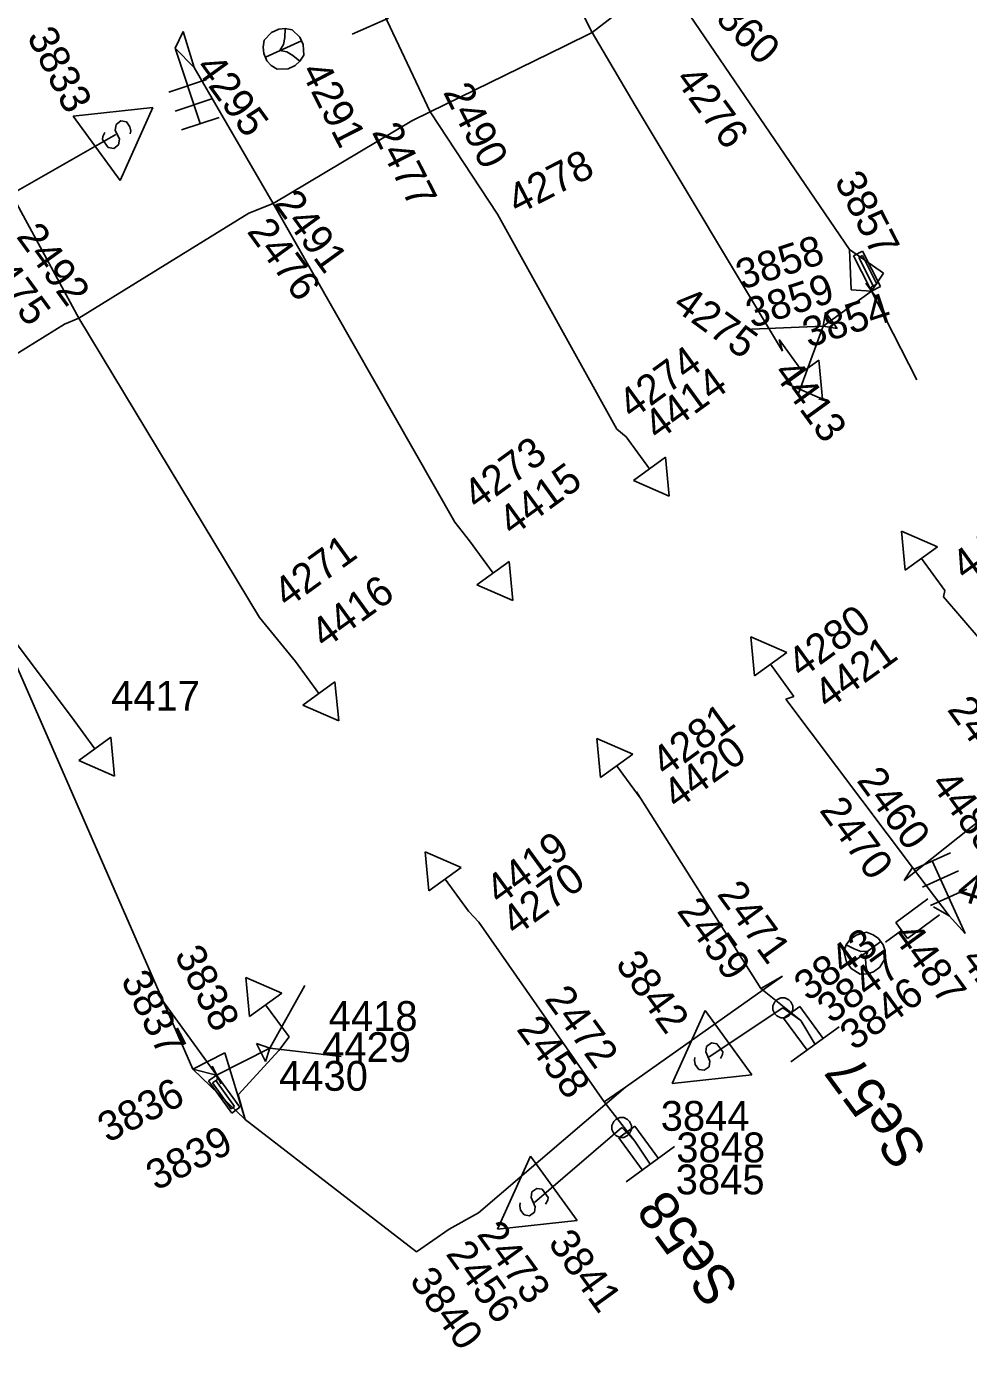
# Model space of a CAD drawing. Extents: x -535557 to -534097, y -1142175 to -1136716.
# Drawn here: x -534895.4 to -534871.72, y -1139172.92 to -1139139.7 of the extents above; entities that cross this region are included whole.
import ezdxf

# ---------------------------------------------------------------- set-up
doc = ezdxf.new("R2010")
doc.units = 0
doc.layers.add('Default', color=7, linetype='Continuous')
doc.layers.add('SS_SZDC', color=7, linetype='Continuous')

# ---------------------------------------------------------------- blocks, each defined once
blk = doc.blocks.new('POINT_DISPLAY')
at = {"layer": 'Default'}
blk.add_line((0, 0), (0, 0), dxfattribs=at)

msp = doc.modelspace()

# ---------------------------------------------------------------- linework, layer by layer
at = {"layer": 'SS_SZDC'}
for p, q in [((-534881.18, -1139139.86), (-534882.97, -1139136.26)), ((-534886.949, -1139138.25), (-534885.25, -1139141.85)), ((-534881.18, -1139139.86), (-534879.569, -1139138.61)), ((-534878.97, -1139139.069), (-534874.71, -1139145.309)), ((-534889.236, -1139139.855), (-534889.054, -1139139.773)), ((-534889.054, -1139139.773), (-534888.897, -1139139.756)), ((-534888.906, -1139139.98), (-534888.897, -1139139.756)), ((-534888.897, -1139139.756), (-534888.719, -1139139.786)), ((-534888.719, -1139139.786), (-534888.525, -1139139.973)), ((-534886.296, -1139139.498), (-534887.211, -1139139.901)), ((-534891.659, -1139140.25), (-534891.46, -1139139.829)), ((-534891.46, -1139139.829), (-534891.18, -1139140.739)), ((-534889.453, -1139140.227), (-534889.423, -1139140.049)), ((-534889.423, -1139140.049), (-534889.236, -1139139.855)), ((-534888.484, -1139140.064), (-534889.395, -1139140.475)), ((-534888.935, -1139140.158), (-534888.906, -1139139.98)), ((-534888.525, -1139139.973), (-534888.443, -1139140.155)), ((-534881.88, -1139140.2), (-534881.18, -1139139.86)), ((-534881.18, -1139139.86), (-534880.1, -1139141.69)), ((-534891.18, -1139140.739), (-534891.659, -1139140.25)), ((-534891.659, -1139140.25), (-534891.029, -1139142.148)), ((-534889.436, -1139140.384), (-534889.453, -1139140.227)), ((-534889.354, -1139140.566), (-534889.436, -1139140.384)), ((-534889.031, -1139140.311), (-534888.935, -1139140.158)), ((-534889.031, -1139140.311), (-534888.853, -1139140.34)), ((-534888.853, -1139140.34), (-534888.7, -1139140.436)), ((-534888.7, -1139140.436), (-534888.526, -1139140.577)), ((-534888.431, -1139140.424), (-534888.526, -1139140.577)), ((-534888.443, -1139140.155), (-534888.431, -1139140.424)), ((-534885.25, -1139141.85), (-534881.88, -1139140.2)), ((-534891.18, -1139140.739), (-534889.199, -1139144.159)), ((-534889.247, -1139140.683), (-534889.354, -1139140.566)), ((-534889.094, -1139140.778), (-534889.247, -1139140.683)), ((-534888.825, -1139140.766), (-534889.094, -1139140.778)), ((-534888.643, -1139140.684), (-534888.825, -1139140.766)), ((-534888.526, -1139140.577), (-534888.643, -1139140.684)), ((-534890.87, -1139141.041), (-534891.819, -1139141.356)), ((-534892.219, -1139141.744), (-534894.223, -1139141.963)), ((-534893.047, -1139143.581), (-534892.219, -1139141.744)), ((-534890.712, -1139141.515), (-534891.661, -1139141.831)), ((-534880.1, -1139141.69), (-534876.399, -1139147.87)), ((-534894.223, -1139141.963), (-534893.047, -1139143.581)), ((-534893.024, -1139142.081), (-534893.146, -1139142.17)), ((-534892.885, -1139142.103), (-534893.024, -1139142.081)), ((-534892.797, -1139142.225), (-534892.885, -1139142.103)), ((-534890.555, -1139141.99), (-534891.504, -1139142.305)), ((-534889.199, -1139144.159), (-534885.71, -1139142.079)), ((-534885.71, -1139142.079), (-534885.25, -1139141.85)), ((-534885.25, -1139141.85), (-534883.56, -1139144.42)), ((-534895.789, -1139143.93), (-534893.149, -1139142.42)), ((-534893.48, -1139142.474), (-534893.429, -1139142.375)), ((-534893.146, -1139142.17), (-534893.168, -1139142.309)), ((-534893.168, -1139142.309), (-534893.061, -1139142.541)), ((-534892.778, -1139142.335), (-534892.797, -1139142.225)), ((-534892.789, -1139142.405), (-534892.778, -1139142.335)), ((-534893.491, -1139142.544), (-534893.48, -1139142.474)), ((-534893.344, -1139142.747), (-534893.491, -1139142.544)), ((-534893.205, -1139142.769), (-534893.344, -1139142.747)), ((-534893.083, -1139142.681), (-534893.205, -1139142.769)), ((-534893.061, -1139142.541), (-534893.083, -1139142.681)), ((-534894.079, -1139147.04), (-534896.02, -1139143.469)), ((-534894.079, -1139147.04), (-534889.81, -1139144.399)), ((-534889.81, -1139144.399), (-534889.199, -1139144.159)), ((-534889.199, -1139144.159), (-534884.63, -1139152.17)), ((-534883.56, -1139144.42), (-534880.56, -1139149.829)), ((-534874.71, -1139145.309), (-534874.67, -1139146.329)), ((-534874.71, -1139145.309), (-534873.859, -1139145.909)), ((-534874.613, -1139145.468), (-534874.391, -1139145.355)), ((-534874.391, -1139145.355), (-534873.937, -1139146.246)), ((-534873.025, -1139148.587), (-534874.613, -1139145.468)), ((-534874.39, -1139145.467), (-534874.479, -1139145.512)), ((-534874.479, -1139145.512), (-534874.116, -1139146.225)), ((-534874.027, -1139146.18), (-534874.39, -1139145.467)), ((-534873.859, -1139145.909), (-534874.159, -1139146.36)), ((-534874.159, -1139146.36), (-534875.373, -1139147.241)), ((-534874.67, -1139146.329), (-534874.159, -1139146.36)), ((-534874.013, -1139146.562), (-534874.306, -1139146.157)), ((-534874.16, -1139146.248), (-534874.027, -1139146.18)), ((-534874.159, -1139146.36), (-534874.16, -1139146.248)), ((-534873.937, -1139146.246), (-534874.159, -1139146.36)), ((-534894.439, -1139147.19), (-534894.079, -1139147.04)), ((-534894.079, -1139147.04), (-534889.539, -1139154.569)), ((-534875.373, -1139147.241), (-534875.318, -1139146.892)), ((-534875.318, -1139146.892), (-534875.024, -1139147.296)), ((-534897.81, -1139149.27), (-534894.439, -1139147.19)), ((-534875.373, -1139147.241), (-534877.174, -1139147.314)), ((-534875.373, -1139147.241), (-534875.999, -1139148.932)), ((-534875.373, -1139147.241), (-534875.024, -1139147.296)), ((-534876.399, -1139147.87), (-534876.479, -1139147.579)), ((-534876.479, -1139147.579), (-534875.892, -1139148.389)), ((-534875.487, -1139148.095), (-534876.296, -1139148.682)), ((-534875.392, -1139149.076), (-534875.487, -1139148.095)), ((-534876.296, -1139148.682), (-534875.392, -1139149.076)), ((-534880.56, -1139149.829), (-534880.329, -1139150.02)), ((-534880.329, -1139150.02), (-534879.742, -1139150.829)), ((-534879.337, -1139150.535), (-534880.146, -1139151.122)), ((-534879.242, -1139151.516), (-534879.337, -1139150.535)), ((-534880.146, -1139151.122), (-534879.242, -1139151.516)), ((-534884.63, -1139152.17), (-534884.26, -1139152.639)), ((-534872.503, -1139152.787), (-534873.407, -1139152.393)), ((-534873.407, -1139152.393), (-534873.312, -1139153.374)), ((-534884.26, -1139152.639), (-534883.672, -1139153.449)), ((-534873.312, -1139153.374), (-534872.503, -1139152.787)), ((-534872.319, -1139153.889), (-534872.907, -1139153.08)), ((-534883.267, -1139153.155), (-534884.076, -1139153.742)), ((-534883.172, -1139154.136), (-534883.267, -1139153.155)), ((-534884.076, -1139153.742), (-534883.172, -1139154.136)), ((-534872.319, -1139153.889), (-534872.35, -1139154.049)), ((-534868.989, -1139157.969), (-534872.35, -1139154.049)), ((-534889.539, -1139154.569), (-534888.64, -1139155.67)), ((-534895.96, -1139154.809), (-534894.27, -1139157.059)), ((-534876.293, -1139155.447), (-534877.197, -1139155.053)), ((-534877.197, -1139155.053), (-534877.102, -1139156.034)), ((-534895.72, -1139155.6), (-534891.22, -1139165.92)), ((-534888.64, -1139155.67), (-534888.052, -1139156.479)), ((-534877.102, -1139156.034), (-534876.293, -1139155.447)), ((-534876.109, -1139156.549), (-534876.697, -1139155.74)), ((-534887.647, -1139156.185), (-534888.456, -1139156.772)), ((-534887.552, -1139157.166), (-534887.647, -1139156.185)), ((-534876.31, -1139156.62), (-534876.109, -1139156.549)), ((-534876.31, -1139156.62), (-534873.13, -1139160.85)), ((-534894.27, -1139157.059), (-534893.682, -1139157.869)), ((-534888.456, -1139156.772), (-534887.552, -1139157.166)), ((-534893.277, -1139157.575), (-534894.086, -1139158.162)), ((-534893.182, -1139158.556), (-534893.277, -1139157.575)), ((-534880.163, -1139157.997), (-534881.067, -1139157.603)), ((-534881.067, -1139157.603), (-534880.972, -1139158.584)), ((-534880.972, -1139158.584), (-534880.163, -1139157.997)), ((-534894.086, -1139158.162), (-534893.182, -1139158.556)), ((-534879.979, -1139159.1), (-534880.567, -1139158.29)), ((-534870.17, -1139158.649), (-534873.34, -1139161.18)), ((-534876.939, -1139163.889), (-534880.069, -1139158.95)), ((-534880.069, -1139158.95), (-534879.979, -1139159.1)), ((-534884.473, -1139160.847), (-534885.377, -1139160.453)), ((-534885.377, -1139160.453), (-534885.282, -1139161.434)), ((-534873.088, -1139160.892), (-534872.177, -1139160.481)), ((-534871.81, -1139162.51), (-534872.633, -1139160.687)), ((-534885.282, -1139161.434), (-534884.473, -1139160.847)), ((-534873.34, -1139161.18), (-534873.13, -1139160.85)), ((-534873.13, -1139160.85), (-534872.21, -1139162.069)), ((-534872.882, -1139161.348), (-534871.971, -1139160.937)), ((-534884.289, -1139161.95), (-534884.877, -1139161.14)), ((-534873.553, -1139162.231), (-534872.748, -1139161.638)), ((-534872.677, -1139161.804), (-534871.765, -1139161.392)), ((-534884.289, -1139161.95), (-534884.029, -1139162.229)), ((-534872.451, -1139162.041), (-534873.256, -1139162.634)), ((-534872.21, -1139162.069), (-534872.6, -1139161.84)), ((-534884.029, -1139162.229), (-534880.88, -1139166.739)), ((-534873.256, -1139162.634), (-534873.553, -1139162.231)), ((-534872.21, -1139162.069), (-534871.81, -1139162.51)), ((-534874.798, -1139162.795), (-534874.707, -1139162.666)), ((-534874.732, -1139163.306), (-534873.927, -1139162.713)), ((-534874.707, -1139162.666), (-534874.546, -1139162.548)), ((-534874.546, -1139162.548), (-534874.285, -1139162.48)), ((-534874.285, -1139162.48), (-534874.115, -1139162.541)), ((-534874.115, -1139162.541), (-534873.986, -1139162.632)), ((-534873.986, -1139162.632), (-534873.868, -1139162.793)), ((-534873.405, -1139162.433), (-534873.807, -1139162.729)), ((-534874.859, -1139162.965), (-534874.798, -1139162.795)), ((-534874.791, -1139163.226), (-534874.859, -1139162.965)), ((-534874.599, -1139162.897), (-534874.798, -1139162.795)), ((-534874.429, -1139162.959), (-534874.599, -1139162.897)), ((-534874.249, -1139162.95), (-534874.429, -1139162.959)), ((-534874.249, -1139162.95), (-534874.31, -1139163.12)), ((-534873.868, -1139162.793), (-534873.819, -1139162.944)), ((-534873.819, -1139162.944), (-534873.81, -1139163.124)), ((-534874.673, -1139163.387), (-534874.791, -1139163.226)), ((-534874.31, -1139163.12), (-534874.302, -1139163.3)), ((-534874.302, -1139163.3), (-534874.264, -1139163.52)), ((-534873.952, -1139163.353), (-534874.113, -1139163.471)), ((-534873.81, -1139163.124), (-534873.952, -1139163.353)), ((-534888.983, -1139164.007), (-534889.887, -1139163.613)), ((-534889.887, -1139163.613), (-534889.792, -1139164.594)), ((-534876.399, -1139163.579), (-534880.34, -1139166.37)), ((-534876.939, -1139163.889), (-534876.399, -1139163.579)), ((-534874.444, -1139163.529), (-534874.673, -1139163.387)), ((-534874.264, -1139163.52), (-534874.444, -1139163.529)), ((-534874.113, -1139163.471), (-534874.264, -1139163.52)), ((-534889.792, -1139164.594), (-534888.983, -1139164.007)), ((-534889.283, -1139165.389), (-534888.4, -1139163.817)), ((-534875.939, -1139164.7), (-534876.939, -1139163.889)), ((-534892.089, -1139164.047), (-534890.032, -1139166.879)), ((-534888.8, -1139165.11), (-534889.387, -1139164.3)), ((-534876.64, -1139164.329), (-534876.59, -1139164.229)), ((-534876.64, -1139164.429), (-534876.64, -1139164.329)), ((-534876.59, -1139164.229), (-534876.54, -1139164.179)), ((-534876.54, -1139164.179), (-534876.44, -1139164.129)), ((-534876.44, -1139164.129), (-534876.34, -1139164.129)), ((-534876.37, -1139164.637), (-534875.965, -1139164.344)), ((-534876.34, -1139164.129), (-534876.24, -1139164.179)), ((-534876.24, -1139164.179), (-534876.19, -1139164.229)), ((-534876.19, -1139164.229), (-534876.14, -1139164.329)), ((-534876.14, -1139164.329), (-534876.14, -1139164.429)), ((-534875.965, -1139164.344), (-534875.377, -1139165.153)), ((-534878.342, -1139164.448), (-534879.17, -1139166.285)), ((-534877.166, -1139166.066), (-534878.342, -1139164.448)), ((-534876.39, -1139164.379), (-534878.239, -1139165.61)), ((-534876.59, -1139164.529), (-534876.64, -1139164.429)), ((-534876.54, -1139164.579), (-534876.59, -1139164.529)), ((-534876.44, -1139164.629), (-534876.54, -1139164.579)), ((-534876.34, -1139164.629), (-534876.44, -1139164.629)), ((-534875.939, -1139164.7), (-534876.39, -1139164.379)), ((-534875.782, -1139165.446), (-534876.37, -1139164.637)), ((-534876.24, -1139164.579), (-534876.34, -1139164.629)), ((-534876.19, -1139164.529), (-534876.24, -1139164.579)), ((-534876.14, -1139164.429), (-534876.19, -1139164.529)), ((-534875.579, -1139165.299), (-534875.939, -1139164.7)), ((-534876.186, -1139165.74), (-534874.973, -1139164.859)), ((-534889.283, -1139165.389), (-534889.619, -1139165.279)), ((-534889.392, -1139165.725), (-534889.619, -1139165.279)), ((-534888.8, -1139165.11), (-534889.06, -1139165.45)), ((-534878.328, -1139165.488), (-534878.306, -1139165.348)), ((-534878.306, -1139165.348), (-534878.184, -1139165.26)), ((-534878.184, -1139165.26), (-534878.045, -1139165.282)), ((-534878.045, -1139165.282), (-534877.898, -1139165.485)), ((-534891.22, -1139165.92), (-534890.409, -1139165.51)), ((-534890.619, -1139166.069), (-534889.283, -1139165.389)), ((-534890.409, -1139165.51), (-534889.899, -1139167.19)), ((-534889.06, -1139165.45), (-534890.079, -1139166.569)), ((-534889.283, -1139165.389), (-534889.392, -1139165.725)), ((-534889.283, -1139165.389), (-534887.492, -1139165.599)), ((-534878.6, -1139165.624), (-534878.611, -1139165.694)), ((-534878.611, -1139165.694), (-534878.592, -1139165.804)), ((-534878.221, -1139165.72), (-534878.328, -1139165.488)), ((-534877.909, -1139165.555), (-534877.96, -1139165.654)), ((-534877.898, -1139165.485), (-534877.909, -1139165.555)), ((-534889.899, -1139167.19), (-534891.22, -1139165.92)), ((-534891.22, -1139165.92), (-534890.619, -1139166.069)), ((-534890.733, -1139165.847), (-534890.506, -1139166.292)), ((-534878.592, -1139165.804), (-534878.504, -1139165.926)), ((-534878.504, -1139165.926), (-534878.365, -1139165.948)), ((-534878.365, -1139165.948), (-534878.243, -1139165.859)), ((-534878.243, -1139165.859), (-534878.221, -1139165.72)), ((-534890.822, -1139166.216), (-534890.619, -1139166.069)), ((-534890.234, -1139167.025), (-534890.822, -1139166.216)), ((-534890.601, -1139166.18), (-534890.723, -1139166.268)), ((-534890.723, -1139166.268), (-534890.252, -1139166.915)), ((-534890.171, -1139166.856), (-534890.642, -1139166.209)), ((-534890.619, -1139166.069), (-534890.601, -1139166.18)), ((-534879.17, -1139166.285), (-534877.166, -1139166.066)), ((-534890.079, -1139166.569), (-534889.899, -1139167.19)), ((-534880.34, -1139166.37), (-534884.039, -1139169.53)), ((-534880.34, -1139166.37), (-534880.88, -1139166.739)), ((-534890.252, -1139166.915), (-534890.171, -1139166.856)), ((-534890.032, -1139166.879), (-534890.234, -1139167.025)), ((-534880.88, -1139166.739), (-534880.109, -1139167.729)), ((-534889.899, -1139167.19), (-534885.6, -1139170.51)), ((-534880.689, -1139167.339), (-534880.639, -1139167.239)), ((-534880.689, -1139167.439), (-534880.689, -1139167.339)), ((-534880.639, -1139167.239), (-534880.589, -1139167.189)), ((-534880.589, -1139167.189), (-534880.489, -1139167.139)), ((-534880.51, -1139167.647), (-534880.105, -1139167.354)), ((-534880.489, -1139167.139), (-534880.389, -1139167.139)), ((-534880.389, -1139167.139), (-534880.289, -1139167.189)), ((-534880.289, -1139167.189), (-534880.239, -1139167.239)), ((-534880.239, -1139167.239), (-534880.189, -1139167.339)), ((-534880.189, -1139167.339), (-534880.189, -1139167.439)), ((-534880.105, -1139167.354), (-534879.517, -1139168.163)), ((-534880.439, -1139167.389), (-534882.63, -1139169.27)), ((-534880.639, -1139167.539), (-534880.689, -1139167.439)), ((-534880.589, -1139167.589), (-534880.639, -1139167.539)), ((-534880.489, -1139167.639), (-534880.589, -1139167.589)), ((-534879.922, -1139168.456), (-534880.51, -1139167.647)), ((-534880.389, -1139167.639), (-534880.489, -1139167.639)), ((-534880.109, -1139167.729), (-534880.439, -1139167.389)), ((-534880.289, -1139167.589), (-534880.389, -1139167.639)), ((-534880.239, -1139167.539), (-534880.289, -1139167.589)), ((-534880.189, -1139167.439), (-534880.239, -1139167.539)), ((-534880.326, -1139168.75), (-534879.113, -1139167.869)), ((-534880.109, -1139167.729), (-534879.72, -1139168.309)), ((-534882.732, -1139168.108), (-534883.56, -1139169.945)), ((-534881.556, -1139169.726), (-534882.732, -1139168.108)), ((-534882.718, -1139169.148), (-534882.696, -1139169.008)), ((-534882.696, -1139169.008), (-534882.574, -1139168.92)), ((-534882.574, -1139168.92), (-534882.435, -1139168.942)), ((-534882.435, -1139168.942), (-534882.288, -1139169.145)), ((-534882.99, -1139169.284), (-534883.001, -1139169.354)), ((-534883.001, -1139169.354), (-534882.982, -1139169.464)), ((-534882.611, -1139169.38), (-534882.718, -1139169.148)), ((-534882.299, -1139169.215), (-534882.35, -1139169.314)), ((-534882.288, -1139169.145), (-534882.299, -1139169.215)), ((-534884.039, -1139169.53), (-534884.779, -1139169.94)), ((-534882.982, -1139169.464), (-534882.894, -1139169.586)), ((-534882.894, -1139169.586), (-534882.755, -1139169.608)), ((-534882.755, -1139169.608), (-534882.633, -1139169.519)), ((-534882.633, -1139169.519), (-534882.611, -1139169.38)), ((-534884.779, -1139169.94), (-534885.6, -1139170.51)), ((-534883.56, -1139169.945), (-534881.556, -1139169.726))]:
    msp.add_line(p, q, dxfattribs=at)

# ---------------------------------------------------------------- block references
for p in [(-534891.46, -1139139.829), (-534881.18, -1139139.86), (-534891.659, -1139140.25), (-534888.939, -1139140.27), (-534881.88, -1139140.2), (-534891.18, -1139140.739), (-534880.1, -1139141.69), (-534885.71, -1139142.079), (-534885.25, -1139141.85), (-534893.149, -1139142.42), (-534889.81, -1139144.399), (-534889.199, -1139144.159), (-534883.56, -1139144.42), (-534874.71, -1139145.309), (-534873.859, -1139145.909), (-534874.67, -1139146.329), (-534874.159, -1139146.36), (-534894.079, -1139147.04), (-534894.439, -1139147.19), (-534876.479, -1139147.579), (-534876.399, -1139147.87), (-534880.56, -1139149.829), (-534880.329, -1139150.02), (-534884.63, -1139152.17), (-534884.26, -1139152.639), (-534872.35, -1139154.049), (-534872.319, -1139153.889), (-534889.539, -1139154.569), (-534888.64, -1139155.67), (-534876.31, -1139156.62), (-534876.109, -1139156.549), (-534894.27, -1139157.059), (-534880.069, -1139158.95), (-534879.979, -1139159.1), (-534873.13, -1139160.85), (-534873.34, -1139161.18), (-534884.289, -1139161.95), (-534872.6, -1139161.84), (-534884.029, -1139162.229), (-534872.21, -1139162.069), (-534871.81, -1139162.51), (-534874.329, -1139163.01), (-534876.399, -1139163.579), (-534876.939, -1139163.889), (-534876.39, -1139164.379), (-534876.39, -1139164.379), (-534875.939, -1139164.7), (-534888.8, -1139165.11), (-534875.579, -1139165.299), (-534890.409, -1139165.51), (-534889.06, -1139165.45), (-534878.239, -1139165.61), (-534891.22, -1139165.92), (-534890.619, -1139166.069), (-534890.079, -1139166.569), (-534880.34, -1139166.37), (-534880.88, -1139166.739), (-534889.899, -1139167.19), (-534880.439, -1139167.389), (-534880.439, -1139167.389), (-534880.109, -1139167.729), (-534879.72, -1139168.309), (-534882.63, -1139169.27), (-534884.039, -1139169.53), (-534884.779, -1139169.94), (-534885.6, -1139170.51)]:
    msp.add_blockref('POINT_DISPLAY', p, dxfattribs=at)

# ---------------------------------------------------------------- texts
for s, height, rotation, p in [('3860', 0.75, 315, (-534878.502, -1139139.14)), ('3833', 0.75, 297, (-534895.399, -1139139.953)), ('4295', 0.75, 306, (-534891.18, -1139140.739)), ('4291', 0.75, 297, (-534888.519, -1139140.824)), ('2490', 0.75, 297, (-534884.939, -1139141.356)), ('4276', 0.75, 306, (-534879.12, -1139141.037)), ('2477', 0.75, 297, (-534886.729, -1139142.358)), ('4278', 0.75, 27, (-534883.063, -1139144.447)), ('3857', 0.75, 297, (-534875.104, -1139143.58)), ('2491', 0.75, 306, (-534889.199, -1139144.159)), ('2492', 0.75, 306, (-534895.673, -1139144.988)), ('2476', 0.75, 306, (-534889.876, -1139144.861)), ('3858', 0.75, 18, (-534877.417, -1139146.33)), ('2475', 0.75, 306, (-534896.655, -1139145.485)), ('3859', 0.75, 18, (-534877.166, -1139147.296)), ('4275', 0.75, 324, (-534879.188, -1139146.782)), ('3854', 0.75, 18, (-534875.742, -1139147.788)), ('4274', 0.75, 36, (-534880.176, -1139149.602)), ('4414', 0.75, 36, (-534879.53, -1139150.138)), ('4413', 0.75, 306, (-534876.652, -1139148.418)), ('4273', 0.75, 36, (-534884.071, -1139151.882)), ('4415', 0.75, 36, (-534883.187, -1139152.542)), ('4422', 0.75, 36, (-534871.802, -1139153.66)), ('4271', 0.75, 36, (-534888.841, -1139154.346)), ('4416', 0.75, 36, (-534887.905, -1139155.369)), ('4280', 0.75, 36, (-534875.924, -1139156.114)), ('4421', 0.75, 36, (-534875.256, -1139156.898)), ('2469', 0.75, 306, (-534872.277, -1139156.882)), ('4281', 0.75, 36, (-534879.337, -1139158.592)), ('4420', 0.75, 36, (-534879.053, -1139159.41)), ('2460', 0.75, 306, (-534874.552, -1139158.665)), ('4488', 0.75, 306, (-534872.694, -1139158.752)), ('2470', 0.75, 306, (-534875.488, -1139159.414)), ('4419', 0.75, 36, (-534883.509, -1139161.813)), ('4270', 0.75, 36, (-534883.108, -1139162.597)), ('4426', 0.75, 342, (-534872.059, -1139161.638)), ('2471', 0.75, 306, (-534878.064, -1139161.526)), ('2459', 0.75, 306, (-534879.07, -1139161.947)), ('3843', 0.75, 36, (-534875.753, -1139164.235)), ('4487', 0.75, 306, (-534873.647, -1139162.578)), ('3838', 0.75, 297, (-534891.69, -1139163.046)), ('3842', 0.75, 306, (-534880.617, -1139163.282)), ('3847', 0.75, 36, (-534875.172, -1139164.797)), ('4286', 0.75, 306, (-534871.931, -1139163.173)), ('3837', 0.75, 297, (-534893.039, -1139163.676)), ('3846', 0.75, 36, (-534874.6, -1139165.474)), ('2472', 0.75, 306, (-534882.396, -1139164.16)), ('2458', 0.75, 306, (-534883.101, -1139164.919)), ('Se57', 1, 126.3757, (-534872.725, -1139167.941)), ('3836', 0.75, 27, (-534893.358, -1139167.784)), ('3839', 0.75, 27, (-534892.143, -1139168.988)), ('Se58', 1, 126.3757, (-534877.455, -1139171.401)), ('2473', 0.75, 306, (-534884.099, -1139170.08)), ('3841', 0.75, 306, (-534882.309, -1139170.296)), ('2456', 0.75, 306, (-534884.879, -1139170.568)), ('3840', 0.75, 306, (-534885.791, -1139171.24))]:
    msp.add_text(s, height=height, rotation=rotation, dxfattribs=at).set_placement(p)
for s, p in [('4417', (-534893.27, -1139156.909)), ('4418', (-534887.8, -1139164.96)), ('4429', (-534887.966, -1139165.742)), ('4430', (-534889.049, -1139166.464)), ('3844', (-534879.458, -1139167.47)), ('3848', (-534879.067, -1139168.263)), ('3845', (-534879.08, -1139169.068))]:
    msp.add_text(s, height=0.75, dxfattribs=at).set_placement(p)

doc.saveas('drawing.dxf')
